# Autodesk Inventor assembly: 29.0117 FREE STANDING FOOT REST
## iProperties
Created: 2007-06
Part Number: 29.0117 FREE STANDING FOOT REST
Document SubType Name: Assembly
Designer: Andy Moles
Author: Andy Moles
